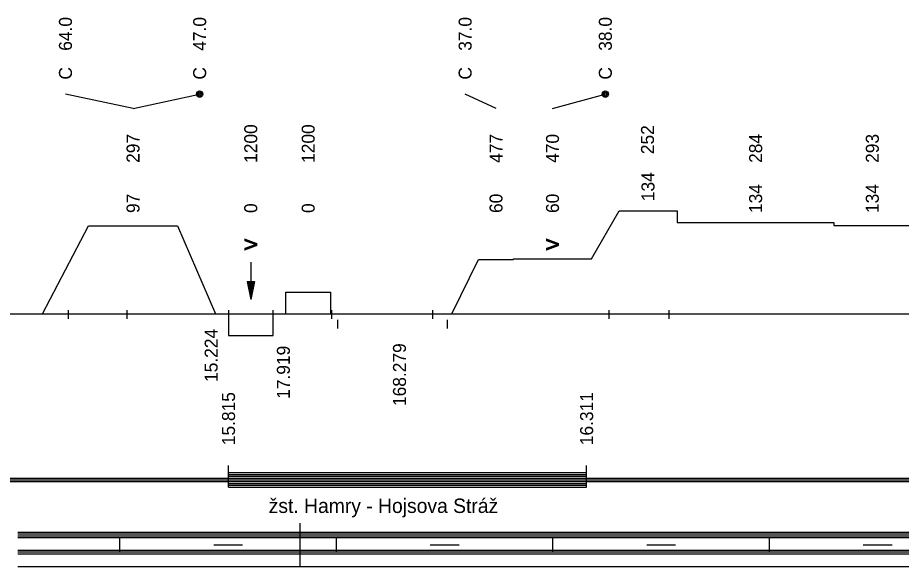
# Model space of a CAD drawing. Extents: x 2 to 10148, y 0 to 380.
# Drawn here: x 1850.8 to 1973.3, y 0 to 76.1 of the extents above; entities that cross this region are included whole.
import ezdxf

# ---------------------------------------------------------------- set-up
doc = ezdxf.new("R2010")
doc.units = 0
for name, color, linetype in [('KRIV1_CARA', 7, 'Continuous'), ('KRIV1_TEXT', 7, 'Continuous'), ('L_OBJEKTY_TEXT', 7, 'Continuous'), ('L_OBJEKTY_TVAR', 7, 'Continuous'), ('RAM', 7, 'Continuous'), ('STAN_CARA', 7, 'Continuous')]:
    doc.layers.add(name, color=color, linetype=linetype)

msp = doc.modelspace()

# ---------------------------------------------------------------- linework, layer by layer
for p, q in [((1857.81, 35.51), (1857.81, 34.32)), ((1865.98, 35.51), (1865.98, 34.32)), ((1880.03, 35.51), (1880.03, 34.32)), ((1886.21, 35.51), (1886.21, 34.32)), ((1894.31, 35.51), (1894.31, 34.32)), ((1908.33, 35.51), (1908.33, 34.32)), ((1932.75, 35.51), (1932.75, 34.32)), ((1941.07, 35.51), (1941.07, 34.32)), ((1895.17, 34.19), (1895.17, 33)), ((1910.34, 34.19), (1910.34, 33))]:
    msp.add_line(p, q)
at = {"layer": 'KRIV1_CARA'}
for p, q in [((1930.37, 42.66), (1934.17, 49.29)), ((1934.17, 49.29), (1942.23, 49.29)), ((1942.23, 49.29), (1942.23, 47.68)), ((1854.25, 35), (1860.65, 47.23)), ((1860.65, 47.23), (1873, 47.23)), ((1873, 47.23), (1878.25, 35)), ((1942.23, 47.68), (1963.96, 47.68)), ((1963.96, 47.68), (1963.96, 47.29)), ((1963.96, 47.29), (1974.58, 47.29)), ((1910.99, 35), (1914.69, 42.55)), ((1914.69, 42.55), (1919.54, 42.55)), ((1919.54, 42.55), (1919.54, 42.66)), ((1919.54, 42.66), (1930.37, 42.66)), ((1888.01, 35), (1888.01, 38)), ((1888.01, 38), (1894.17, 38)), ((1894.17, 38), (1894.17, 35)), ((1245.39, 35), (1850.83, 35)), ((1850.83, 35), (2170.83, 35)), ((1880.05, 35), (1880.05, 32)), ((1886.22, 32), (1886.22, 35)), ((1880.05, 32), (1886.22, 32))]:
    msp.add_line(p, q, dxfattribs=at)
at = {"layer": 'KRIV1_TEXT'}
for p, q in [((1866.82, 63.5), (1857.45, 65.5)), ((1866.82, 63.5), (1876.05, 65.5)), ((1917.12, 63.5), (1912.84, 65.5)), ((1924.95, 63.5), (1932.27, 65.5)), ((1883.13, 42.2), (1883.13, 42.2)), ((1883.13, 42.2), (1883.13, 40)), ((1882.63, 39.5), (1883.13, 37)), ((1882.63, 39.5), (1883.63, 39.5)), ((1882.73, 39.5), (1883.13, 37.5)), ((1882.83, 39.5), (1883.13, 38)), ((1882.93, 39.5), (1883.13, 38.5)), ((1883.03, 39.5), (1883.13, 39)), ((1883.13, 40), (1883.13, 37)), ((1883.63, 39.5), (1883.13, 37)), ((1883.53, 39.5), (1883.13, 37.5)), ((1883.43, 39.5), (1883.13, 38)), ((1883.33, 39.5), (1883.13, 38.5)), ((1883.23, 39.5), (1883.13, 39)), ((1883.13, 39.5), (1883.13, 39.5)), ((1883.13, 39.5), (1883.13, 39.5))]:
    msp.add_line(p, q, dxfattribs=at)
for centre, radius in [((1876.05, 65.5), 0.45), ((1876.05, 65.5), 0.3), ((1876.05, 65.5), 0.15), ((1932.27, 65.5), 0.45), ((1932.27, 65.5), 0.3), ((1932.27, 65.5), 0.15)]:
    msp.add_circle(centre, radius, dxfattribs=at)
at = {"layer": 'L_OBJEKTY_TVAR'}
for p, q in [((1880.05, 11), (1880.05, 14)), ((1929.68, 11), (1929.68, 14)), ((1880.05, 13), (1929.68, 13)), ((1880.05, 12.75), (1929.68, 12.75)), ((1880.05, 12.5), (1929.68, 12.5)), ((1880.05, 12.25), (1929.68, 12.25)), ((1880.05, 12), (1929.68, 12)), ((1880.05, 11.75), (1929.68, 11.75)), ((1880.05, 11.5), (1929.68, 11.5)), ((1880.05, 11.25), (1929.68, 11.25)), ((1880.05, 11), (1929.68, 11))]:
    msp.add_line(p, q, dxfattribs=at)
at = {"layer": 'RAM'}
for p, q in [((1890, 0), (1890, 6)), ((1850.83, 4.75), (2170.83, 4.75)), ((1850.83, 4.5), (2170.83, 4.5)), ((1850.83, 4.25), (2170.83, 4.25)), ((1850.83, 4), (2170.83, 4)), ((1865, 2), (1865, 4)), ((1895, 2), (1895, 4)), ((1925, 2), (1925, 4)), ((1955, 2), (1955, 4)), ((1878, 3), (1882, 3)), ((1908, 3), (1912, 3)), ((1938, 3), (1942, 3)), ((1968, 3), (1972, 3)), ((1850.83, 2.25), (2170.83, 2.25)), ((1850.83, 2), (2170.83, 2)), ((1850.83, 1.75), (2170.83, 1.75)), ((1850.83, 0), (2170.83, 0))]:
    msp.add_line(p, q, dxfattribs=at)
at = {"layer": 'STAN_CARA'}
for p, q in [((1799.78, 12.25), (1850.83, 12.25)), ((1850.83, 12.25), (2170.83, 12.25)), ((1799.78, 12), (1850.83, 12)), ((1799.78, 12), (1850.83, 12)), ((1799.78, 11.75), (1850.83, 11.75)), ((1850.83, 12), (2170.83, 12)), ((1850.83, 12), (2170.83, 12)), ((1850.83, 11.75), (2170.83, 11.75))]:
    msp.add_line(p, q, dxfattribs=at)

# ---------------------------------------------------------------- texts
at = {"layer": 'KRIV1_TEXT'}
for s, p in [('64.0', (1858.35, 71.5)), ('47.0', (1876.95, 71.5)), ('37.0', (1913.74, 71.5)), ('38.0', (1933.17, 71.5)), ('C', (1858.35, 67.5)), ('C', (1876.95, 67.5)), ('C', (1913.74, 67.5)), ('C', (1933.17, 67.5)), ('1200', (1884.03, 55.95)), ('1200', (1891.99, 55.95)), ('252', (1939.01, 57.16)), ('297', (1867.72, 55.95)), ('477', (1918.02, 55.95)), ('470', (1925.85, 55.95)), ('284', (1954, 55.95)), ('293', (1970.17, 55.95)), ('134', (1939.08, 50.64)), ('134', (1954, 49)), ('134', (1970.17, 49)), ('97', (1867.72, 49)), ('60', (1918.02, 49)), ('60', (1925.85, 49)), ('0', (1884.03, 49)), ('0', (1891.99, 49)), ('V', (1884.03, 43.9)), ('V', (1884.03, 43.75)), ('V', (1925.85, 43.9)), ('V', (1925.85, 43.75)), ('15.224', (1878.54, 25.57)), ('168.279', (1904.64, 22.23)), ('17.919', (1888.55, 23.23))]:
    msp.add_text(s, height=1.8, rotation=90, dxfattribs=at).set_placement(p)
at = {"layer": 'L_OBJEKTY_TEXT'}
for s, p in [('15.815', (1880.95, 16.8)), ('16.311', (1930.58, 16.8))]:
    msp.add_text(s, height=1.8, rotation=90, dxfattribs=at).set_placement(p)
msp.add_text('žst. Hamry - Hojsova Stráž', height=2, dxfattribs=at).set_placement((1885.62, 7.4))

doc.saveas('drawing.dxf')
